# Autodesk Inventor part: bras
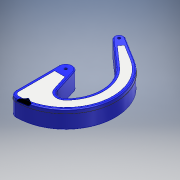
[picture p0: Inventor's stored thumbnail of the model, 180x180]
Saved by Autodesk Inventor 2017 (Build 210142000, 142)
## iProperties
Created: 2013-10
Part Number: bras
Material: Plastique ABS
Document SubType Name: Modeling
Designer: Bruno
Density: 1.06 g/cm^3
Appearance: Bleu - Peinture murale - Brillant
Mass: 68.244 g
Surface Area: 169.292 cm^2
Volume: 64.3811 cm^3
Sending System: SolidWorks 2013
Last Author: christophe
Last Saved: 2014-02-15
Author: Bruno
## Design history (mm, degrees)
node "Symétrie2"
feature "Balayage3"
node "Solide1"
node "Solide2"
